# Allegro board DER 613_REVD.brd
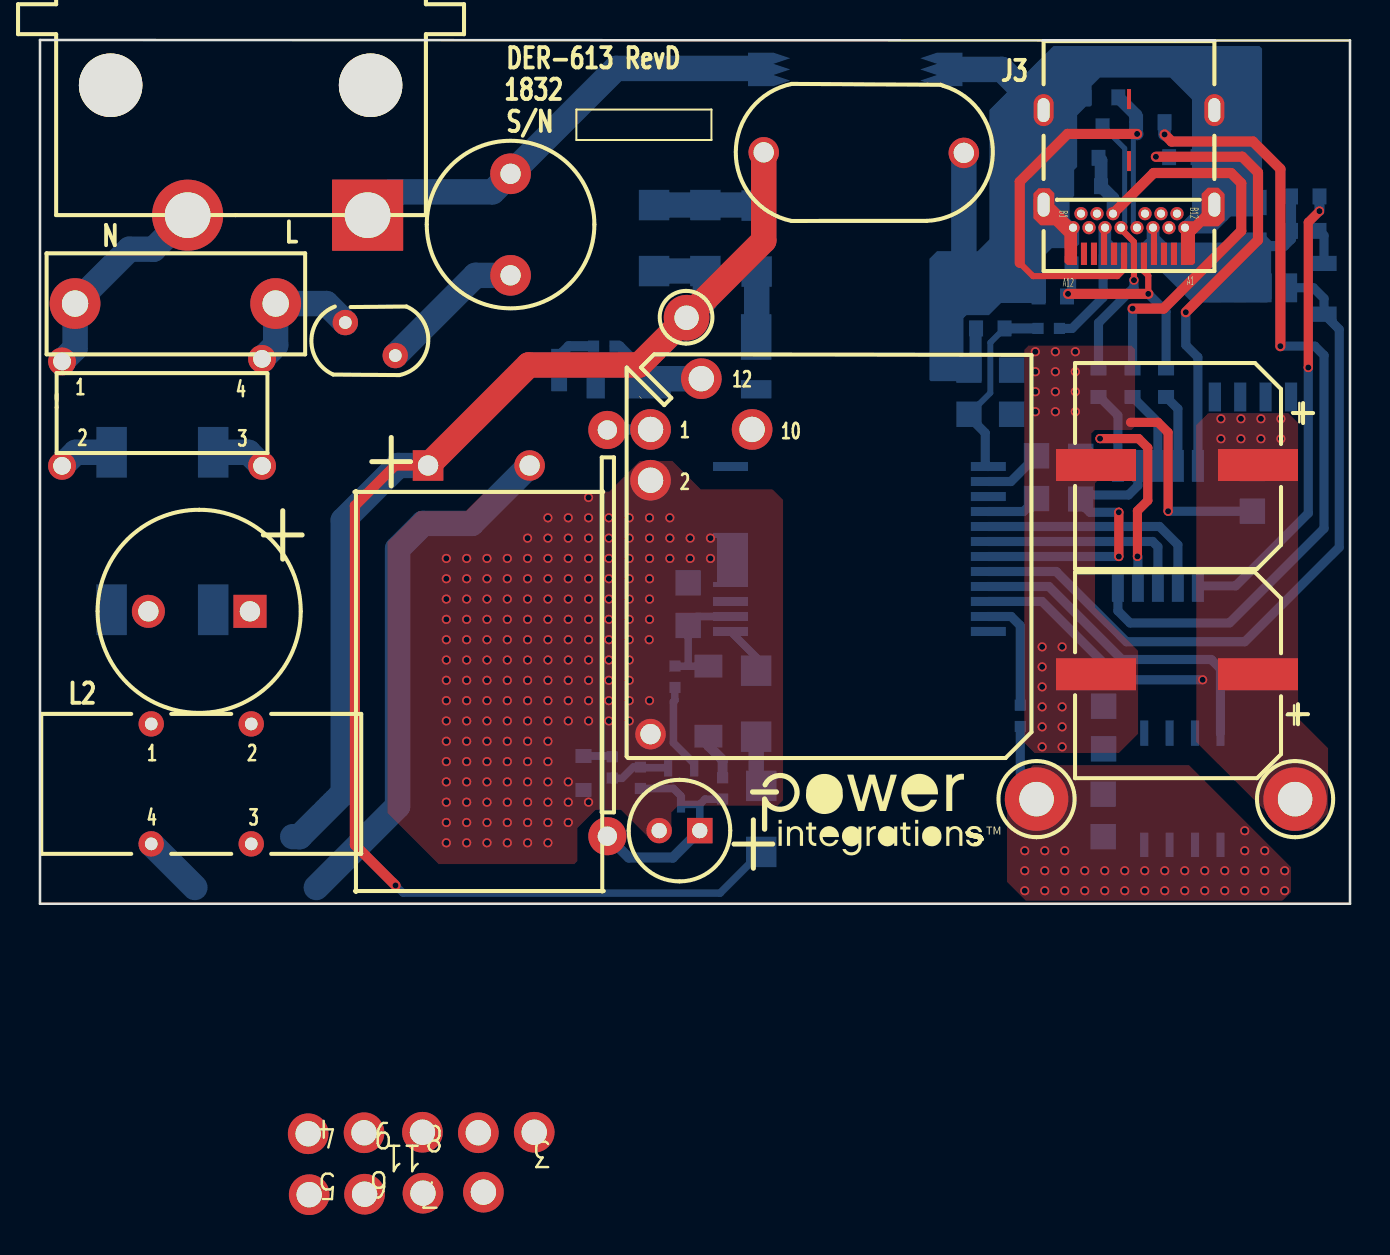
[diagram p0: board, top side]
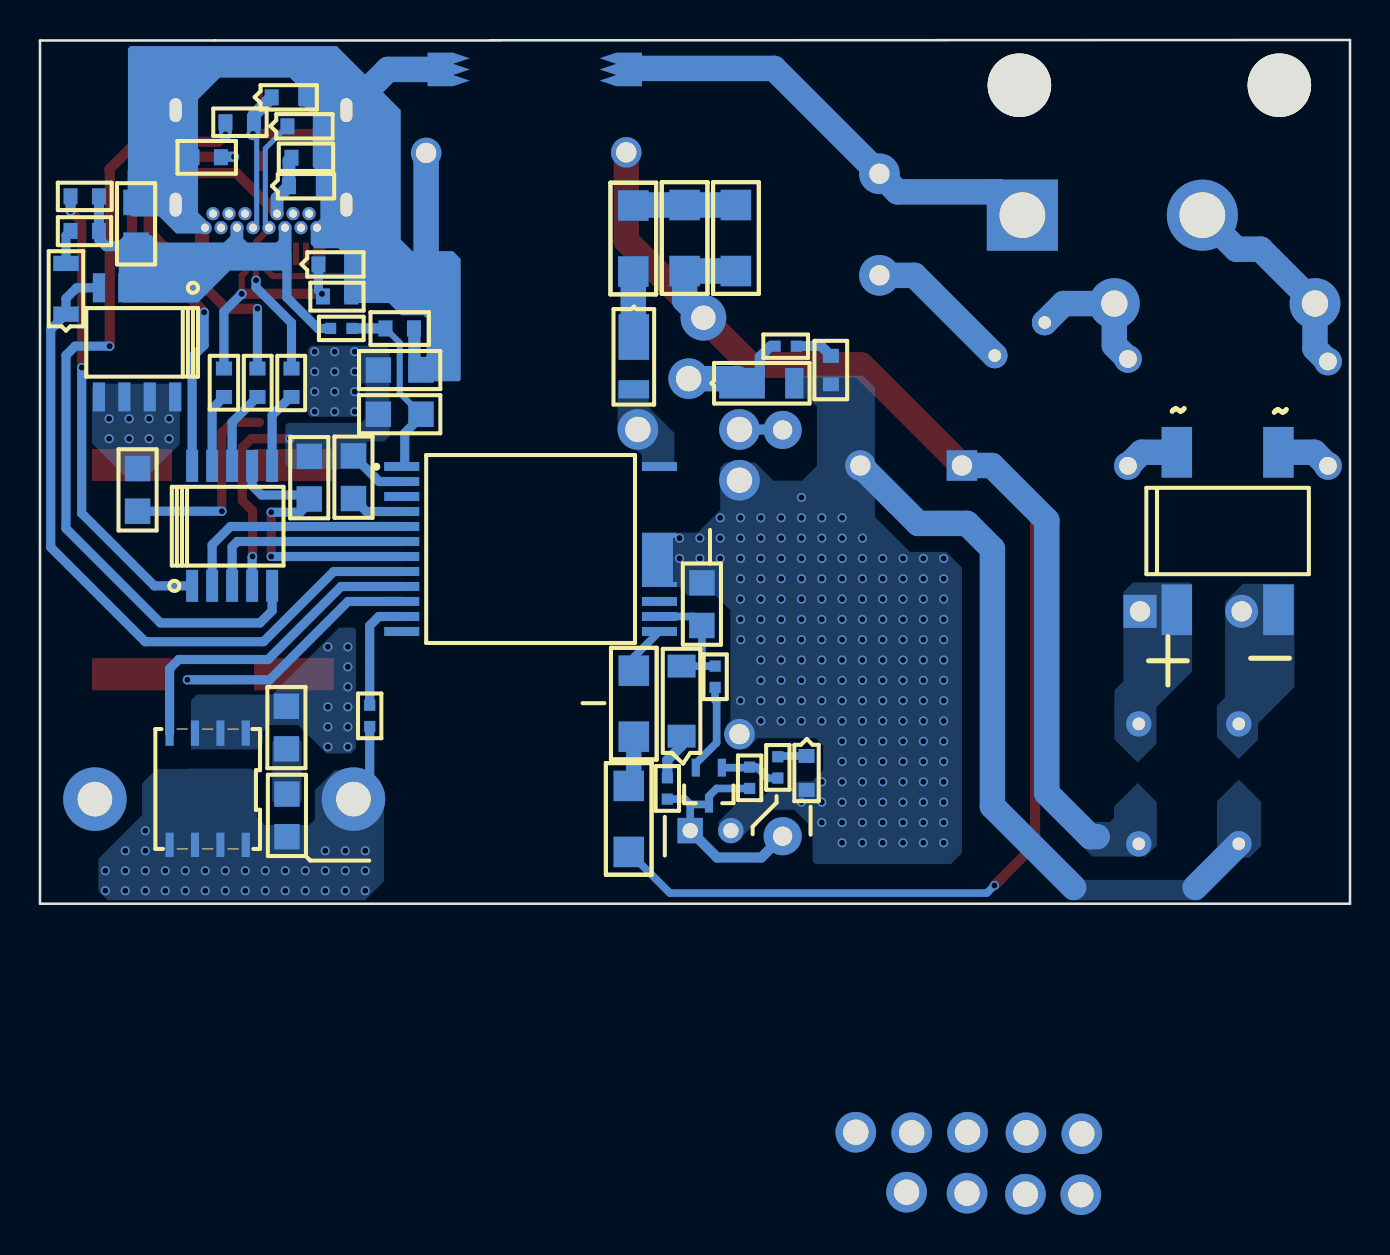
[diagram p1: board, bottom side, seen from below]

Outline 65.51 x 43.21 mm; copper layers: TOP, BOTTOM. Coordinates in mm from the lower left corner of the outline.
Outline path: 0,43.21 56.77,43.18 65.51,43.18 65.51,0 0,0 0,43.21

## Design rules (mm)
constraint set DEFAULT: min track width 0.254

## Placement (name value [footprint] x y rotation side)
BR1  DF206ST-G  [PISMDDFS]  8.66 14.76 0 bottom
C1  100 nF  [PI_NP_XCAP_RAD512X197X395D040]  1.75 30.02 0 top
C2  15 uF  [PIPOLCAPCYLD400LS200040]  10.5 14.63 180 top
C3  33 uF  [PIPOLCAPCLYD500LS200040800LH]  19.41 21.92 0 top
C4  2.2 nF  [PISMC1206]  33.27 34.95 270 bottom
C5  56 pF  [PISMC0603]  25.96 27.41 270 bottom
C6  22  uF  [PIPOLCAPCLYD200LS80030]  32.99 3.66 180 top
C7  470 nF  [PISMC0805]  32.41 13.92 90 bottom
C8  330 pF  [PINPCAPRAD394X275394030]  36.19 37.59 359.8 top
C9  1 nF  [PISMC0805]  53.19 7.75 90 bottom
C10  470 uF  [PISMCPAN1VA]  60.91 11.48 180 top
C11  470 uF  [PISMCPAN1VA]  60.91 21.95 180 top
C12  2.2 uF  [PISMC0805]  49.83 22.4 270 bottom
C13  1 uF  [PISMC0805]  60.63 21.77 270 bottom
C14  2.2 uF  [PISMC0805]  52.04 22.38 270 bottom
C15  560 pF  [PISMC0603]  51.36 30.38 180 bottom
C16  560 pF  [PISMC0603]  52.93 37.31 180 bottom
C17  1 uF  [PISMC0805]  60.71 32.94 90 bottom
C18  4.7 uF  [PISMC0805]  46.46 24.49 0 bottom
D1  DFLR1600-7  [PISMDDFLR120012]  35.81 28.37 90 bottom
D2  DFLR1200-7  [PISMDDFLR120012]  30.43 26.04 0 bottom
D3  BAV21WS-7-F  [PISMSOD323]  64.21 29.49 90 bottom
D4  DZ2J240M0L  [PI_SM_D_SSMINI2P]  51.59 31.98 180 bottom
D5  DZ2J240M0L  [PI_SM_D_SSMINI2P]  53.06 35.89 180 bottom
D6  DZ2J240M0L  [PI_SM_D_SSMINI2P]  53.14 38.89 180 bottom
D7  DZ2J240M0L  [PI_SM_D_SSMINI2P]  53.92 40.34 180 bottom
F1  3.15 A  [PI_TR5_SUBMIN_FUSE]  23.53 31.43 90 top
FL1  Hole_50mils  [PI_HOLE_50MIL]  32.33 29.31 0 top
FL2  Hole_70mils  [PI_HOLE_70MIL]  62.76 5.21 0 top
FL3  Hole_70mils  [PI_HOLE_70MIL]  49.83 5.21 0 top
J1  CON2  [PI_PWR_CONN_2P_RTANG]  10.03 34.44 90 top
J3  CON24_USB_C  [PI_CONN_USBC_WURTH]  54.46 34.52 180 top
JP1  J  [PI_JUMPER800]  28.37 3.38 90 top
L1  108 uH  [PI_TOROID_CM_CHOKE_4P]  -0.06 31.69 270 top
L2  16.6 mH  [PI_TOROID_CMC15X7_4P_V]  5.56 9.5 0 top
NOREF  -  []  0 0 0 top
NOREF#2  -  []  -150.53 59.24 0 top
NOREF#3  -  []  65.51 0 90 top
NOREF#4  -  []  35.59 6.3 0 top
Q1  MMST3904  [PISMSOT323132]  31.39 6.81 0 bottom
Q2  TSM160N10LCR  [PISMPQFN5X6B]  55.22 8.53 0 bottom
Q3  AO4354  [PISMSO8]  58.75 30.81 0 bottom
R1  205 k  [PISMR1206]  30.71 34.95 270 bottom
R2  14.7  [PISMR1206]  35.84 31.62 90 bottom
R3  130.0 k  [PISMR0402]  30.02 5.77 90 bottom
R4  3.24 k  [PISMR0402]  31.75 10.82 90 bottom
R5  22  [PISMR0402]  34.14 5.23 90 bottom
R6  2.00 M  [PISMR1206]  36.07 5.89 270 bottom
R7  1.80 M  [PISMR1206]  35.81 11.66 270 bottom
R8  100  [PISMR0402]  28.75 27.89 180 bottom
R9  5.6  [PISMR0805]  53.16 5.49 270 bottom
R10  47  [PISMR0402]  49.02 8.86 90 bottom
R11  0.009  [PISMR0805]  48.59 26.7 180 bottom
R12  100  [PISMR0603]  63.98 33.66 180 bottom
R13  10 k  [PISMR0603]  63.98 35.38 180 bottom
R14  22  [PISMR0603]  56.31 26.77 270 bottom
R15  22  [PISMR0603]  54.64 26.77 270 bottom
R16  22  [PISMR0603]  52.93 25.35 90 bottom
R17  22  [PISMR0603]  56.24 39.09 180 bottom
R18  160.0 k  [PISMR0402]  50.98 28.78 180 bottom
R19  10  [PISMR0603]  48.23 28.78 180 bottom
R20  7.15 k  [PISMR0402]  28.61 6.29 90 bottom
RT1  5  [PI_RAD_276DX197T_LS100D025]  17.77 28.25 180 top
RT2  100 k  [PISMR0603]  57.89 37.34 180 bottom
T1  RM8  [PI_BOBBIN_RM8_12P_CLP]  30.53 23.72 180 top
U1  INN3366C  [PI_IC_INSOP_24D]  47.42 21.87 180 bottom
U2  WT6635P  [PISMSOP10]  57.9 15.9 180 bottom
VR1  DZ2S08200L  [PI_SM_D_SSMINI2P]  27.18 7.39 270 bottom
VR2  MMSZ5260BT1G  [PI_SM_SOD-123_12]  33.43 8.38 90 bottom

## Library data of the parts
BR1 = DIODE BRIDGE_+-~~
C1 = CAP NP: alternate symbols: (pi_np_xcap_rad512x197x395d040_h)
C2 = CAP POL: alternate symbols: (pipolcapclyd400x630ls200030h)
C3 = CAP POL: alternate symbols: (pipolcapclyd500ls200040800lh)
C4 C5 C7 C8 C12-C18 = CAP NP
C6 = CAP POL: alternate symbols: (pipolcapclyd200ls80030h)
C9 = CAP NP: alternate symbols: (pismc0805_1)
C10 C11 = CAP POL
D1-D3 = DIODE
D4-D7 VR1 VR2 = DIODE_ZENER
F1 = FUSE
FL1-FL3 = FlyingLead
J1 = CON2
J3 = CON24_USB
JP1 = JUMPER_1
L1 = INDUCTOR_4P_1-2_4-3
L2 = TORRID 4P_14_23
Q1 = NPN_BEC
Q2 Q3 = FET_N_SGD_123_4_5678
R1-R20 = R
RT1 = THERMISTOR: alternate symbols: (pi_rad_276DX197Tls100d025H)
RT2 = THERMISTOR
T1 = BRM8_12P_CLP_0: alternate symbols: (pi_bobbin_rm8_12p_clp)
U1 = DEV_InnoPro
U2 = WT6635P-10

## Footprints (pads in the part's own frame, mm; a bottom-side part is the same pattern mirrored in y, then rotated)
PI_BOBBIN_RM8_12P_CLP
  round 2.032 hole 1.27: 1(0,0) 2(0,2.54) 3(8.611,35.179) 4(17.12,35.23) 5(17.069,38.278) 6(14.3,38.252) 7(11.379,38.202) 8(11.405,35.154) 9(14.326,35.179) 10(-5.08,0) 11(5.817,35.154) 12(-2.54,-2.54) CLP1(8.357,38.151)
  round 1.524 hole 1.016: CLP2(0,15.24)
PI_CONN_USBC_WURTH
  oval 1.001x1.6 hole 0.599x1.199: (-4.27,-0.45) (-4.27,-5.179) (4.27,-0.45) (4.27,-5.179)
  round 0.66 hole 0.406: (-1.999,0.701) (1.999,0.701) B1(2.799,0.701) B2(2.4,0) B3(1.6,0) B4(1.199,0.701) B5(0.8,0) B6(0.399,0.701) B7(-0.399,0.701) B8(-0.8,0) B9(-1.199,0.701) B10(-1.6,0) B11(-2.4,0) B12(-2.799,0.701)
  rect 0.305x1.118 smd: A1(-2.751,2.009) A2(-2.25,2.009) A3(-1.75,2.009) A4(-1.25,2.009) A5(-0.749,2.009) A6(-0.249,2.009) A7(0.249,2.009) A8(0.749,2.009) A9(1.25,2.009) A10(1.75,2.009) A11(2.25,2.009) A12(2.751,2.009)
PI_HOLE_50MIL
  round 2.286 hole 1.219: 1(0,0)
PI_HOLE_70MIL
  round 3.175 hole 1.727: 1(0,0.025)
PI_IC_INSOP_24D
  rect 1.75x0.45 smd: 1(0,0) 2(0,-0.749) 3(0,-1.501) 4(0,-2.25) 5(0,-3) 6(0,-3.749) 7(0,-4.501) 8(0,-5.25) 9(0,-6) 10(0,-6.749) 11(0,-7.501) 12(0,-8.25) 13(12.89,-8.25) 14(12.89,-7.501) 15(12.89,-6.749) 24(12.89,0)
  custom 0.437x0.437 smd: 16(12.89,-4.671)
PI_JUMPER800
  round 1.905 hole 0.965: 1(0,0) 2(20.32,0)
PI_NP_XCAP_RAD512X197X395D040
  round 2.54 hole 1.321: 1(0,0) 2(10.033,0)
PI_PWR_CONN_2P_RTANG
  round 3.175 hole 3.175 unplated: (6.5,6.5) (6.5,-6.5)
  rect 3.556x3.556 hole 2.286: 1(0,-6.35)
  round 3.556 hole 2.286: 2(0,2.649)
PI_RAD_276DX197T_LS100D025
  round 1.27 hole 0.635: 1(0,0.826) 2(2.499,-0.826)
PI_SM_D_SSMINI2P
  rect 0.699x0.8 smd: 1(0,0) 2(1.699,0)
PI_SM_SOD-123_12
  rect 1.143x1.397 smd: 1(0,0) 2(3.505,0)
PI_TOROID_CM_CHOKE_4P
  round 1.397 hole 0.889: 1(4.564,1.159) 2(9.787,1.159) 3(9.787,11.16) 4(4.437,11.16)
PI_TOROID_CMC15X7_4P_V
  round 1.27 hole 0.635: 1(0,-0.5) 2(5.001,-0.5) 3(5.001,-6.5) 4(0,-6.5)
PI_TR5_SUBMIN_FUSE
  round 2.032 hole 1.016: 1(0,0) 2(5.08,0)
PINPCAPRAD394X275394030
  round 1.524 hole 1.016: 1(0,0) 2(10.008,0)
PIPOLCAPCLYD200LS80030
  rect 1.27x1.27 hole 0.762: 1(0,0)
  round 1.27 hole 0.762: 2(2.032,0)
PIPOLCAPCLYD500LS200040800LH
  rect 1.524x1.524 hole 1.016: 1(0,0)
  round 1.524 hole 1.016: 2(5.08,0)
PIPOLCAPCYLD400LS200040
  rect 1.651x1.651 hole 1.016: 1(0,0)
  round 1.651 hole 1.016: 2(5.08,0)
PISMC0603
  rect 0.699x0.8 smd: 1(0,0) 2(1.422,0)
PISMC0805
  rect 1.27x1.27 smd: 1(0,0) 2(2.134,0)
PISMC1206
  rect 1.524x1.524 smd: 1(0,0) 2(3.302,0)
PISMCPAN1VA
  rect 4x1.6 smd: 1(0,0) 2(8.1,0)
PISMDDFLR120012
  rect 2.286x1.524 smd: 1(-0.025,0)
  rect 0.914x1.524 smd: 2(-2.642,0)
PISMDDFS
  rect 1.524x2.54 smd: 1(0,0.051) 2(-5.08,0.051) 3(0,-7.823) 4(-5.08,-7.823)
PISMPQFN5X6B
  rect 0.406x1.27 smd: 1(0,0) 2(1.27,0) 3(2.54,0) 4(3.81,0)
  rect 0.406x1.219 smd: 5(3.81,5.588) 6(2.54,5.588) 7(1.27,5.588) 8(0,5.588)
PISMR0402
  rect 0.559x0.559 smd: 1(0,0) 2(1.067,0)
PISMR0603
  rect 0.699x0.8 smd: 1(0,0) 2(1.422,0)
PISMR0805
  rect 1.27x1.27 smd: 1(0,0) 2(2.134,0)
PISMR1206
  rect 1.524x1.524 smd: 1(0,0) 2(3.302,0)
PISMSO8
  rect 0.61x1.448 smd: 1(0,0) 2(1.27,0) 3(2.54,0) 4(3.81,0) 5(3.81,5.461) 6(2.54,5.461) 7(1.27,5.461) 8(0,5.461)
PISMSOD323
  rect 0.762x1.27 smd: 1(0,0) 2(2.54,0)
PISMSOP10
  rect 0.599x1.6 smd: 1(0,0) 2(1.001,0) 3(1.999,0) 4(3,0) 5(4,0) 6(4,6) 7(3,6) 8(1.999,6) 9(1.001,6) 10(0,6)
PISMSOT323132
  rect 0.406x0.889 smd: 1(0.018,0) 2(1.321,0) 3(0.66,1.803)

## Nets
VBUS_IN: C17.1 J3.A4 J3.A9 J3.B4 J3.B9(VBUS4) Q3.1 Q3.2 Q3.3(S3) R12.2 R13.2 R18.1
NC3: U1.3
S: C9.2 C10.2 C11.2 C12.1 C13.2 C14.1 C18.2 Q2.1 Q2.2 Q2.3(S3) R11.1 U1.2 U2.4(VSS)
N2044610: BR1.1 C2.1 L2.2
N2052921: C10.1 C11.1 C13.1 FL2.1 Q3.5 Q3.6 Q3.7 Q3.8 U1.10(VOUT)
N2239928: D1.2 T1.10 U1.24
N2240907: C3.1 C4.2 C8.1 FL1.1 L2.3 R1.2 R6.2
N2243875: C3.2 C5.2 C6.2 C7.2 D2.2 L2.4 T1.2 T1.CLP2 U1.16 VR1.2
N2245604: FL3.1 Q2.5 Q2.6 Q2.7 Q2.8 R9.2 R10.1
N2254675: C4.1 R1.1 R2.2
N2401179: C8.2 C15.2 C16.2 C17.2 D4.2 D5.2 D6.2 D7.2 J3.A1 J3.A12 J3.B1 J3.B12 R11.2 R19.2 RT2.1
N2666518: R10.2 U1.11
N2670154: BR1.2 C2.2 L2.1
N2725054: D2.1 R8.1 T1.12
N2729572: Q2.4 U1.9
N2741729: D1.1 R2.1
N2764626: C1.1 J1.2 L1.1
N2930737: BR1.4 L1.2
N2958561: C7.1 R4.2 U1.14 VR2.2
N2986761: F1.1 RT1.1
N2989279: BR1.3 L1.3
N2989341: C1.2 L1.4 RT1.2
N2989363: F1.2 J1.1
N2993096: C6.1 JP1.1 Q1.3 R3.1 R5.1
N2993205: R5.2 VR2.1
N4181205: R6.1 R7.2
N11157505: C12.2 U1.4
N11161568: Q1.1 R3.2 R20.1
N11380339: R7.1 U1.13
N11380424: JP1.2 T1.1
N11390717: Q1.2(EMITTER) R4.1
N11927756: D3.2 R12.1
N11929917: C14.2 U1.7 U2.7
N11929995: U1.5 U2.2
N11930002: U1.6 U2.3
N11989159: R13.1 U2.1
N11989210: RT2.2 U2.10
N12043478: R16.1 U2.6
N12043482: R14.2 U2.9
N12043490: R15.2 U2.8
N12043518: C15.1 D4.1 J3.A5 R14.1
N12043675: C16.1 D5.1 J3.B5 R15.1
N12046357: R17.1 U2.5
N12046915: D7.1 J3.A7 J3.B7 R17.2
N12047298: D6.1 J3.A6 J3.B6 R16.2
N12057942: C18.1 R18.2 R19.1 U1.1
N12067975: D3.1 Q3.4 U1.8
N12148241: R20.2 VR1.1
N27226770: C9.1 R9.1
N27250240: C5.1 R8.2

Pads without a net: J3 A2 A3 A8 A10 A11 B2 B3 B8 B10 B11; T1 3 4 5 6 7 8 9 11 CLP1; U1 12 15

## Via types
v1: diameter 0.457, hole 0.305, TOP to BOTTOM, 239 vias

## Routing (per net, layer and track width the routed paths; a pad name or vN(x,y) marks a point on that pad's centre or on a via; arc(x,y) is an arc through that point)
VBUS_IN: length 11.8
  TOP w0.305: J3.B9 55.71,33.77 J3.A4 ; J3.B4 53.21,33.77 J3.A9
  BOTTOM w0.457: R18.1 51.61,28.78 53.16,30.33 53.16,32.41
  BOTTOM w0.508: R13.2 R12.2 62.56,33.25 62.2,32.89 60.66,32.89
S: length 22.9
  TOP w0.457: v1(56.41,19.63) 56.41,23.57 55.91,24.08 54.53,24.08 ; v1(53.01,23.27) 54.94,23.27 55.4,22.81 55.4,20.17 54.88,19.65 v1(54.88,17.37)
  BOTTOM w0.457: v1(56.41,19.63) C13.2 ; C12.1 48.55,21.12 U1.2 ; v1(54.88,17.37) 54.9,17.35 U2.4
  vias: v1(49.77,27.61) v1(49.77,26.61) v1(49.77,25.61) v1(49.77,24.61) v1(50.11,12.85) v1(50.11,11.85) v1(50.11,10.85) v1(50.11,9.85) v1(50.11,8.85) v1(50.11,7.85) v1(50.77,27.61) v1(50.77,26.61) v1(50.77,25.61) v1(50.77,24.61) v1(51.11,12.85) v1(51.11,9.85) v1(51.11,8.85) v1(51.11,7.85) v1(51.77,27.61) v1(51.77,26.61) v1(51.77,25.61) v1(51.77,24.61)
N2052921: length 12.3
  BOTTOM w0.457: v1(58.14,11.2) 54.03,11.2 50.11,15.12 U1.10
  vias: v1(59.05,24.26) v1(59.05,23.26) v1(60.05,24.26) v1(60.05,23.26) v1(61.05,24.26) v1(61.05,23.26) v1(62.05,24.26) v1(62.05,23.26)
N2240907: length 97.3
  TOP w0.508: v1(17.78,0.91) 15.75,2.95 15.75,19.91 17.75,21.92 C3.1
  TOP w1.27: C8.1 36.19,33.17 FL1.1 29.97,26.95 24.43,26.95 C3.1
  BOTTOM w0.381: v1(17.78,0.91) 18.16,0.53 34.01,0.53 R6.2
  BOTTOM w1.27: R1.2 C4.2 33.27,30.2 32.38,29.31 FL1.1 ; C3.1 17.91,21.92 15.16,19.18 15.16,5.54 12.98,3.36 12.64,3.36
N2243875: length 30.1
  BOTTOM w0.762: 24.43,21.92 C3.2
  BOTTOM w1.27: 13.82,0.81 17.88,4.88 17.88,17.75 19.15,19.02 21.59,19.02 C3.2 ; 7.74,0.81 5.56,2.99
  vias: v1(20.32,17.27) v1(20.32,16.26) v1(20.32,15.24) v1(20.32,14.22) v1(20.32,13.21) v1(20.32,12.19) v1(20.32,11.18) v1(20.32,10.16) v1(20.32,9.14) v1(20.32,8.13) v1(20.32,7.11) v1(20.32,6.1) v1(20.32,5.08) v1(20.32,4.06) v1(20.32,3.05) v1(21.34,17.27) v1(21.34,16.26) v1(21.34,15.24) v1(21.34,14.22) v1(21.34,13.21) v1(21.34,12.19) v1(21.34,11.18) v1(21.34,10.16) v1(21.34,9.14) v1(21.34,8.13) v1(21.34,7.11) v1(21.34,6.1) v1(21.34,5.08) v1(21.34,4.06) v1(21.34,3.05) v1(22.35,17.27) v1(22.35,16.26) v1(22.35,15.24) v1(22.35,14.22) v1(22.35,13.21) v1(22.35,12.19) v1(22.35,11.18) v1(22.35,10.16) v1(22.35,9.14) v1(22.35,8.13) v1(22.35,7.11) v1(22.35,6.1) v1(22.35,5.08) v1(22.35,4.06) v1(22.35,3.05) v1(23.37,17.27) v1(23.37,16.26) v1(23.37,15.24) v1(23.37,14.22) v1(23.37,13.21) v1(23.37,12.19) v1(23.37,11.18) v1(23.37,10.16) v1(23.37,9.14) v1(23.37,8.13) v1(23.37,7.11) v1(23.37,6.1) v1(23.37,5.08) v1(23.37,4.06) v1(23.37,3.05) v1(24.38,18.29) v1(24.38,17.27) v1(24.38,16.26) v1(24.38,15.24) v1(24.38,14.22) v1(24.38,13.21) v1(24.38,12.19) v1(24.38,11.18) v1(24.38,10.16) v1(24.38,9.14) v1(24.38,8.13) v1(24.38,7.11) v1(24.38,6.1) v1(24.38,5.08) v1(24.38,4.06) v1(24.38,3.05) v1(25.4,19.3) v1(25.4,18.29) v1(25.4,17.27) v1(25.4,16.26) v1(25.4,15.24) v1(25.4,14.22) v1(25.4,13.21) v1(25.4,12.19) v1(25.4,11.18) v1(25.4,10.16) v1(25.4,9.14) v1(25.4,8.13) v1(25.4,7.11) v1(25.4,6.1) v1(25.4,5.08) v1(25.4,4.06) v1(25.4,3.05) v1(26.42,19.3) v1(26.42,18.29) v1(26.42,17.27) v1(26.42,16.26) v1(26.42,15.24) v1(26.42,14.22) v1(26.42,13.21) v1(26.42,12.19) v1(26.42,11.18) v1(26.42,10.16) v1(26.42,9.14) v1(26.42,6.1) v1(26.42,5.08) v1(26.42,4.06) v1(27.43,20.32) v1(27.43,19.3) v1(27.43,18.29) v1(27.43,17.27) v1(27.43,16.26) v1(27.43,15.24) v1(27.43,14.22) v1(27.43,13.21) v1(27.43,12.19) v1(27.43,11.18) v1(27.43,10.16) v1(27.43,9.14) v1(27.43,5.08) v1(28.45,19.3) v1(28.45,18.29) v1(28.45,17.27) v1(28.45,16.26) v1(28.45,15.24) v1(28.45,14.22) v1(28.45,13.21) v1(28.45,12.19) v1(28.45,11.18) v1(28.45,10.16) v1(28.45,9.14) v1(29.46,19.3) v1(29.46,18.29) v1(29.46,17.27) v1(29.46,16.26) v1(29.46,15.24) v1(29.46,14.22) v1(29.46,13.21) v1(29.46,12.19) v1(29.46,11.18) v1(29.46,10.16) v1(29.46,9.14) v1(30.48,19.3) v1(30.48,18.29) v1(30.48,17.27) v1(30.48,16.26) v1(30.48,15.24) v1(30.48,14.22) v1(30.46,13.21) v1(30.48,10.16) v1(31.5,19.3) v1(31.5,18.29) v1(31.5,17.27) v1(32.51,18.29) v1(32.51,17.27) v1(33.53,18.29) v1(33.53,17.27)
N2245604: length 4
  BOTTOM w0.457: FL3.1 49.83,5.33 49.02,6.15 R10.1
  vias: v1(49.25,2.65) v1(49.25,1.65) v1(49.25,0.65) v1(50.25,2.65) v1(50.25,1.65) v1(50.25,0.65) v1(51.25,2.65) v1(51.25,1.65) v1(51.25,0.65) v1(52.25,1.65) v1(52.25,0.65) v1(53.25,1.65) v1(53.25,0.65) v1(54.25,1.65) v1(54.25,0.65) v1(55.24,1.65) v1(55.24,0.65) v1(56.24,1.65) v1(56.24,0.65) v1(57.24,1.65) v1(57.24,0.65) v1(58.24,1.65) v1(58.24,0.65) v1(59.24,1.65) v1(59.24,0.65) v1(60.24,3.65) v1(60.24,2.65) v1(60.24,1.65) v1(60.24,0.65) v1(61.24,2.65) v1(61.24,1.65) v1(61.24,0.65) v1(62.25,1.65) v1(62.25,0.65)
N2254675: length 5.1
  BOTTOM w1.27: 35.84,34.92 35.81,34.95 C4.1 R1.1
N2401179: length 19.2
  TOP w0.305: J3.A12 51.71,33.77 J3.B1 51.35,33.82 50.16,35 ; 51.71,33.79 51.66,33.84 ; 58.65,34.72 57.74,33.82 J3.B12 57.21,33.77 J3.A1
  BOTTOM w1.27: C8.2 46.2,30.25 ; 45.52,41.73 48.11,41.73 50.11,39.73
N2666518: length 5.8
  BOTTOM w0.457: R10.2 49.02,13.91 48.56,14.37 U1.11
N2725054: length 5.7
  BOTTOM w0.508: R8.1 28.98,27.89 29.51,27.36 29.51,26.54 30.02,26.04 D2.1
  BOTTOM w1.27: D2.1 30.63,26.26 T1.12
N2729572: length 16.5
  BOTTOM w0.457: Q2.4 59.03,11.76 58.57,12.22 54.1,12.22 50.45,15.87 U1.9
N2741729: length 3.3
  BOTTOM w1.27: R2.1 35.84,28.37 D1.1
N2764626: length 10.6
  BOTTOM w1.27: J1.2 5.68,32.74 4.47,32.74 C1.1 1.75,27.77 L1.1
N2930737: length 2.8
  BOTTOM w1.27: BR1.4 1.78,22.58 L1.2
N2958561: length 6
  BOTTOM w0.381: 32.36,11.89 VR2.2 ; 32.36,11.89 R4.2 ; 32.36,11.89 32.41,11.94 C7.1 32.86,14.37 U1.14
N2986761: length 7.4
  BOTTOM w1.27: F1.1 21.78,31.43 RT1.1
N2989279: length 2.7
  BOTTOM w1.27: BR1.3 10.43,22.58 L1.3
N2989341: length 6.9
  BOTTOM w1.27: RT1.2 14.32,30.02 C1.2 11.79,27.93 L1.4
N2989363: length 22.4
  BOTTOM w1.27: J1.1 17.55,35.61 22.63,35.61 F1.2 28.8,41.78 35.79,41.78
N2993096: length 11.7
  BOTTOM w0.381: R5.1 33.26,5.23 32.99,4.97 ; C6.1 32.99,4.97 ; 32.99,4.97 32.09,4.97 Q1.3 32.05,5.38 31.67,5.77 R3.1
  BOTTOM w0.508: C6.1 31.65,2.31 29.44,2.31 JP1.1
N2993205: length 2.4
  BOTTOM w0.508: VR2.1 33.43,7.9 34.14,7.19 R5.2
N4181205: length 2.6
  BOTTOM w0.762: R6.1 35.81,6.15 R7.2
N11157505: length 2.7
  BOTTOM w0.457: U1.4 49.18,19.62 C12.2
N11161568: length 3
  BOTTOM w0.381: R20.1 28.69,6.29 28.7,6.27 29.11,6.27 29.67,6.83 R3.2 30.05,6.81 Q1.1
N11380339: length 2.5
  BOTTOM w0.381: U1.13 35.81,12.34 R7.1
N11380424: length 2.2
  BOTTOM w0.508: JP1.2 29.11,23.7 29.13,23.72 T1.1
N11390717: length 4.5
  BOTTOM w0.381: Q1.2 32.72,7.01 31.67,8.05 31.67,10.1 31.75,10.17 R4.1
N11927756: length 1.7
  BOTTOM w0.457: D3.2 64.21,33.43 R12.1
N11929917: length 15.2
  TOP w0.457: v1(53.95,17.37) v1(53.95,19.58)
  BOTTOM w0.457: U1.7 v1(53.95,17.37) ; v1(53.95,19.58) 52.5,19.58 52.04,20.04 C14.2 52.25,20.45 54.43,20.45 54.9,20.92 U2.7
N11929995: length 11.9
  BOTTOM w0.457: U1.5 55.98,18.87 56.9,17.95 U2.2
N11930002: length 10.5
  BOTTOM w0.457: U1.6 55.64,18.12 55.9,17.86 U2.3
N11989159: length 23.1
  TOP w0.457: v1(63.42,26.82) 63.42,34.09 v1(63.98,34.65)
  BOTTOM w0.457: U2.1 59.79,15.9 63.42,19.53 v1(63.42,26.82)
  BOTTOM w0.508: R13.1 v1(63.98,34.65)
N11989210: length 22.5
  TOP w0.508: v1(57.3,29.59) 60.91,33.2 60.91,36.58 60.12,37.36 v1(55.8,37.36)
  BOTTOM w0.457: U2.10 57.9,27.34 57.3,27.94 v1(57.3,29.59)
  BOTTOM w0.508: RT2.2 56.34,37.34 56.32,37.36 v1(55.8,37.36)
N12043478: length 3.9
  BOTTOM w0.457: R16.1 52.98,25.35 53.9,24.43 U2.6
N12043482: length 3.7
  BOTTOM w0.457: R14.2 56.9,24.76 U2.9
N12043490: length 4
  BOTTOM w0.457: R15.2 55.9,24.08 U2.8
N12043518: length 11.8
  TOP w0.305: J3.A5 55.21,31.64 55.42,31.42 v1(55.42,30.51)
  TOP w0.508: v1(55.42,30.51) v1(51.41,30.51)
  BOTTOM w0.457: v1(51.41,30.51) 51.59,30.68 D4.1 ; 55.45,30.48 56.31,29.62 R14.1
  BOTTOM w0.508: 55.45,30.48 v1(55.42,30.51)
N12043675: length 23
  TOP w0.508: v1(54.64,29.77) 56.18,29.77 60.07,33.66 60.07,36.04 59.56,36.55 55.69,36.55 J3.B5
  BOTTOM w0.457: R15.1 v1(54.64,29.77)
  BOTTOM w0.635: C16.1 53.06,37.19 D5.1 53.66,35.29 J3.B5
N12046357: length 40.8
  TOP w0.508: v1(62.03,27.89) 62.03,36.75 60.66,38.13 56.59,38.13 v1(56.24,38.48)
  BOTTOM w0.457: v1(62.03,27.89) 63.75,27.89 64.21,27.43 64.21,18.77 59.49,14.05 54.51,14.05 53.9,14.65 U2.5
  BOTTOM w0.635: v1(56.24,38.48) R17.1
N12046915: length 24.4
  TOP w0.305: 49,32.05 49.66,31.39 53.87,31.39 54.21,31.73 J3.A7
  TOP w0.508: v1(54.86,38.51) 51.38,38.51 49,36.12 49,32.05
  BOTTOM w0.254: J3.B7 54.86,33.84 54.67,34.02 54.67,38.32 v1(54.86,38.51)
  BOTTOM w0.635: v1(54.86,38.51) 54.81,38.56 R17.2 54.81,39.45 D7.1
N12047298: length 13.7
  TOP w0.305: v1(54.71,31.19) J3.A6 54.71,33.1 54.06,33.75 J3.B6
  BOTTOM w0.254: D6.1 54.24,37.78 54.24,34.07 54.06,33.89 J3.B6
  BOTTOM w0.457: v1(54.71,31.19) 54.71,30.83 52.93,29.06 R16.2
N12057942: length 9.7
  BOTTOM w0.3: C18.1 47.52,25.55 47.52,28.07 R19.1
  BOTTOM w0.457: U1.1 47.27,22.02 47.27,23.55 46.46,24.36 C18.1
  BOTTOM w0.508: R19.1 R18.2
N12067975: length 35.6
  BOTTOM w0.457: U1.8 50.82,16.62 54.33,13.11 60.25,13.11 64.97,17.83 64.97,28.73 D3.1 64.21,30.28 63.68,30.81 Q3.4
N12148241: length 1.5
  BOTTOM w0.381: VR1.1 28.57,7.39 R20.2
N27250240: length 1.9
  BOTTOM w0.508: C5.1 26.44,27.89 R8.2

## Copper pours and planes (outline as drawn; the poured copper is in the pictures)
VBUS_IN on BOTTOM (solid shape): 53.57,33.88 53.57,33.2 53.7,33.07 55.14,33.07 55.35,33.27 55.35,33.83 55.52,34.01 55.83,34.01 55.98,33.86 55.98,33.4 56.31,33.07 59.59,33.07 59.97,33.45 61.26,33.45 61.57,33.15 61.57,30.28 61.37,30.07 57.61,30.07 56.01,31.67 53.44,31.67 53.26,31.5 53.06,31.5 52.93,31.62 52.93,33.83 53.11,34.01 53.44,34.01
S on TOP: 49.23,8.05 49.73,7.54 53.95,7.54 54.91,8.51 54.91,12.65 52.76,14.81 52.76,21.03 52.91,21.18 54.36,21.18 54.8,21.63 54.8,22.58 54.65,22.73 52.7,22.73 52.58,22.86 52.58,23.53 52.75,23.7 54.58,23.7 54.76,23.88 54.76,27.74 54.58,27.91 49.43,27.91 49.23,27.71
S on BOTTOM: 57.96,7.72 54.69,7.72 54.36,8.05 54.36,8.64 54.05,8.94 52.6,8.94 51.18,7.52 49.96,7.52 49.71,7.77 49.71,13.72 49.81,13.82 50.55,13.82 53.9,10.46 57.66,10.46 57.96,10.16
S on BOTTOM: 52.98,21.74 53.24,22 53.24,23.93 53.11,24.05 49.45,24.05 49.23,24.28 49.23,25.98 49.28,26.04 49.43,26.04 49.5,25.96 49.5,24.54 49.68,24.36 51.99,24.36 52.12,24.49 52.12,27.74 51.94,27.91 48.23,27.91 48.03,27.71 48.03,23.39 48.3,23.13 49.11,23.13 49.17,23.06 49.17,21.92 49.35,21.74
N2044610 on BOTTOM: 9.68,8 10.62,7.06 11.79,8.23 11.79,9.7 10.92,10.57 10.06,10.57 9.68,10.19
N2044610 on BOTTOM: 7.9,11.61 10.21,9.3 11.61,9.3 11.79,9.47 11.79,10.67 11.33,11.13 11.33,15.6 10.85,16.08 8,16.08 7.9,15.98
N2052921 on TOP: 62.92,9.27 62.92,24.05 62.43,24.54 58.42,24.54 57.82,23.94 57.82,8.09 62.18,3.73 63.63,3.73 64.41,4.52 64.41,7.77
N2052921 on BOTTOM: 62.74,26.01 58.72,26.01 58.52,25.81 58.52,22.99 60.17,21.34 61.21,21.34 62.92,23.04 62.92,25.83
N2239928 on BOTTOM: 36.63,26.11 36.63,23.67 35.41,22.45 35.41,21.67 33.83,21.67 33.78,21.72 33.78,23.55 35.08,24.84 35.08,26.14 36.6,26.14
N2240907 on BOTTOM: 9.66,5.09 10.62,6.04 11.57,5.09 11.58,5.09 11.8,4.87 11.8,4.3 12.01,4.08 13.51,4.08 13.69,3.91 13.69,3.17 12.88,2.36 10.22,2.36 9.66,2.92
N2243875 on TOP: 31.62,22.15 30,22.15 28.46,20.61 22.26,20.61 21.29,19.63 18.92,19.63 17.37,18.08 17.37,4.55 19.94,1.98 26.72,1.98 26.87,2.13 26.87,3.78 27.79,4.7 29.06,4.7 30.61,3.15 31.32,3.15 31.57,3.4 31.57,4.57 31.9,4.9 36.88,4.9 37.16,5.18 37.16,20.19 36.63,20.73 33.05,20.73
N2243875 on BOTTOM: 5.56,6.22 6.65,5.12 6.65,2.79 6.17,2.31 5.03,2.31 4.45,2.89 4.45,5.1
N2243875 on BOTTOM: 19.41,16.81 19.41,2.54 19.96,1.98 26.72,1.98 26.87,2.13 26.87,3.78 27.79,4.7 29.06,4.7 30.61,3.15 31.32,3.15 31.57,3.4 31.57,4.11 30.63,5.05 29.64,5.05 29.11,5.59 28.12,5.59 27.58,6.12 26.9,6.12 26.34,6.68 26.34,7.9 26.72,8.28 29.62,8.28 30.14,7.76 30.72,7.76 30.99,8.03 30.99,14.68 31.72,15.42 33.12,15.42 33.55,15.85 35.41,15.85 35.41,18.57 32.61,18.57 31.5,19.68 31.5,21.82 31.24,22.07 29.74,22.07 28.83,21.16 27.41,21.16 26.66,21.91 26.66,24.85 27.08,25.27 27.97,25.27 28.18,25.49 28.18,26.3 28.07,26.42 24.36,26.42 23.76,25.82 23.76,19.35 22.01,17.6 20.19,17.6
N2243875 on BOTTOM: 14.07,0.18 14.83,0.94 14.83,1.35 14.48,1.7 13.82,1.7 13.31,1.19 8.26,1.19 7.85,1.6 7.32,1.6 6.93,1.22 6.93,0.74 7.49,0.18
N2245604 on TOP: 49.3,0.15 48.36,1.09 48.36,5.64 49.66,6.93 57.45,6.93 62.56,1.83 62.56,0.58 62.13,0.15
N2245604 on BOTTOM: 54.97,6.76 58.09,6.76 58.1,6.74 59.68,6.74 60.4,6.02 60.4,4.45 62.59,2.26 62.59,0.64 62.13,0.18 49.25,0.18 48.31,1.12 48.31,5.69 49.3,6.68 50.77,6.68 51.77,5.69 51.77,4.22 52.04,3.94 54.25,3.94 54.66,4.34 54.66,6.45
N2401179 on TOP (solid shape): 50.72,35.53 50.72,34.98 51.59,34.11 51.74,34.11 51.92,33.93 51.92,33.66 51.84,33.58 51.84,31.95 51.36,31.95 51.23,32.08 51.23,33.4 50.7,33.93 50.04,33.93 49.68,34.29 49.68,35.53 49.94,35.79 50.47,35.79
N2401179 on TOP (solid shape): 59.23,35.51 59.23,34.19 58.93,33.88 58.17,33.88 57.76,33.48 57.76,32.05 57.66,31.95 57.07,31.95 57.07,33.53 56.95,33.66 56.95,33.91 57.18,34.14 57.68,34.14 58.09,34.54 58.09,35.51 58.39,35.81 58.93,35.81
N2401179 on BOTTOM (solid shape): 46.13,40.89 44.86,40.89 44.02,41.17 44.86,41.45 44.02,41.73 44.86,42.01 44.02,42.29 44.86,42.57 46.13,42.57
N2401179 on BOTTOM (solid shape): 61.11,42.77 61.11,34.57 60.92,34.38 59.55,34.38 58.7,33.53 57.05,33.53 56.95,33.63 56.95,33.91 57.61,34.57 57.61,40.23 56.52,41.33 53.01,41.33 52.59,40.91 52.59,39.94 52.53,39.88 52.3,39.88 51.87,39.45 51.87,36.86 51.71,36.7 51.71,35.41 51.49,35.18 51.49,34.26 51.64,34.11 51.79,34.11 51.97,33.93 51.97,32.99 51.77,32.79 50.6,32.79 50.3,32.5 50.3,30.05 48.06,30.05 47.45,29.44 46.33,29.44 46.18,29.29 46.18,27.41 46.23,27.36 46.46,27.36 46.48,27.38 46.48,29.16 47.09,29.16 47.09,26.14 44.55,26.14 44.48,26.21 44.48,32.26 44.86,32.64 46.89,32.64 47.47,33.22 47.47,39.7 50.67,42.9 60.99,42.9
N2670154 on BOTTOM: 2.78,10.83 4.83,8.79 6.43,8.79 6.65,9.02 6.65,9.91 6.25,10.31 6.25,15.11 5.36,16 2.82,16 2.78,15.96
N2670154 on BOTTOM: 6.65,8.33 5.56,7.24 4.6,8.2 4.6,10.06 5.13,10.59 5.94,10.59 6.65,9.88
N2989363 on BOTTOM (solid shape): 37.52,42.29 36.68,42.01 37.52,41.73 36.68,41.45 37.52,41.17 36.68,40.89 35.41,40.89 35.41,42.57 36.68,42.57
N27226770 on BOTTOM: 53.64,8.33 52.65,8.33 52.43,8.1 52.43,5.13 52.63,4.93 53.67,4.93 53.9,5.16 53.9,8.08

Small or netless copper shapes (teardrops, artwork), in the pictures only: 2 on TOP

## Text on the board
Ref Des/Silkscreen Top: N | L | 1832 | DER-613 RevD | S/N
User.7: PLEASE DELETE THESE PINS | SLOTS | 13   DOUBLE SIDED MATERIAL FR4 COPPER 2oz THICKNESS 0.062" | 14  FAB HOUSE LOGO DATE CODE TO BE IN SILK SCREEN ONLY.DO NOT USE COPPER.
User.9: FIGURE | FINISHED_SIZE | 12.0 | 16.0 | 25.0 | 30.0 | 35.0 | 38.0 | 40.0 | 48.0 | 50.0 | 52.0 | 68.0 | 90.0 | 125.0 | 47.201x23.598 | DRILL CHART: TOP to BOTTOM | ALL UNITS ARE IN MILS | ROTATION | - | 90.000 | PLATED | NON-PLATED | QTY | 239 | 14 | 6 | 2 | 4 | 9 | 1 | 13
